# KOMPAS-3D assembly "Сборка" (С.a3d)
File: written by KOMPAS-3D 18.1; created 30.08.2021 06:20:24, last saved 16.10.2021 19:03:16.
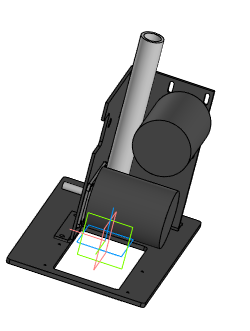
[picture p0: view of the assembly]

Document properties: Автор: 111; Полное имя файла: C:\Users\admin\Desktop\ffb\С.a3d

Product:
- Part/product: Сборка
    Масса: 6.64482
  - Component [detail]: PANEL-MOTOR_default  | Масса: 0.0798691; source file: PANEL-MOTOR.m3d
  - Component [detail]: Деталь  | Масса: 0.647503; source file: 23.m3d
  - Component [detail]: Деталь  | Масса: 1.10029; source file: p1.m3d
  - Component [detail]: Деталь  | Масса: 0.345327; source file: ..\10.cdw, 5.m3d
  - Component [detail]: Деталь  | Масса: 0.198381; source file: s1.m3d
  - Component [detail]: Деталь  | qty 2  | Масса: 2.13673; source file: motor.m3d

Referenced files in C:\Users\admin\Desktop\ffb\: p1.m3d, 23.m3d, 5.m3d, PANEL-MOTOR.m3d, s1.m3d, motor.m3d
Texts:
  Деталь (1)
  Деталь (2)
